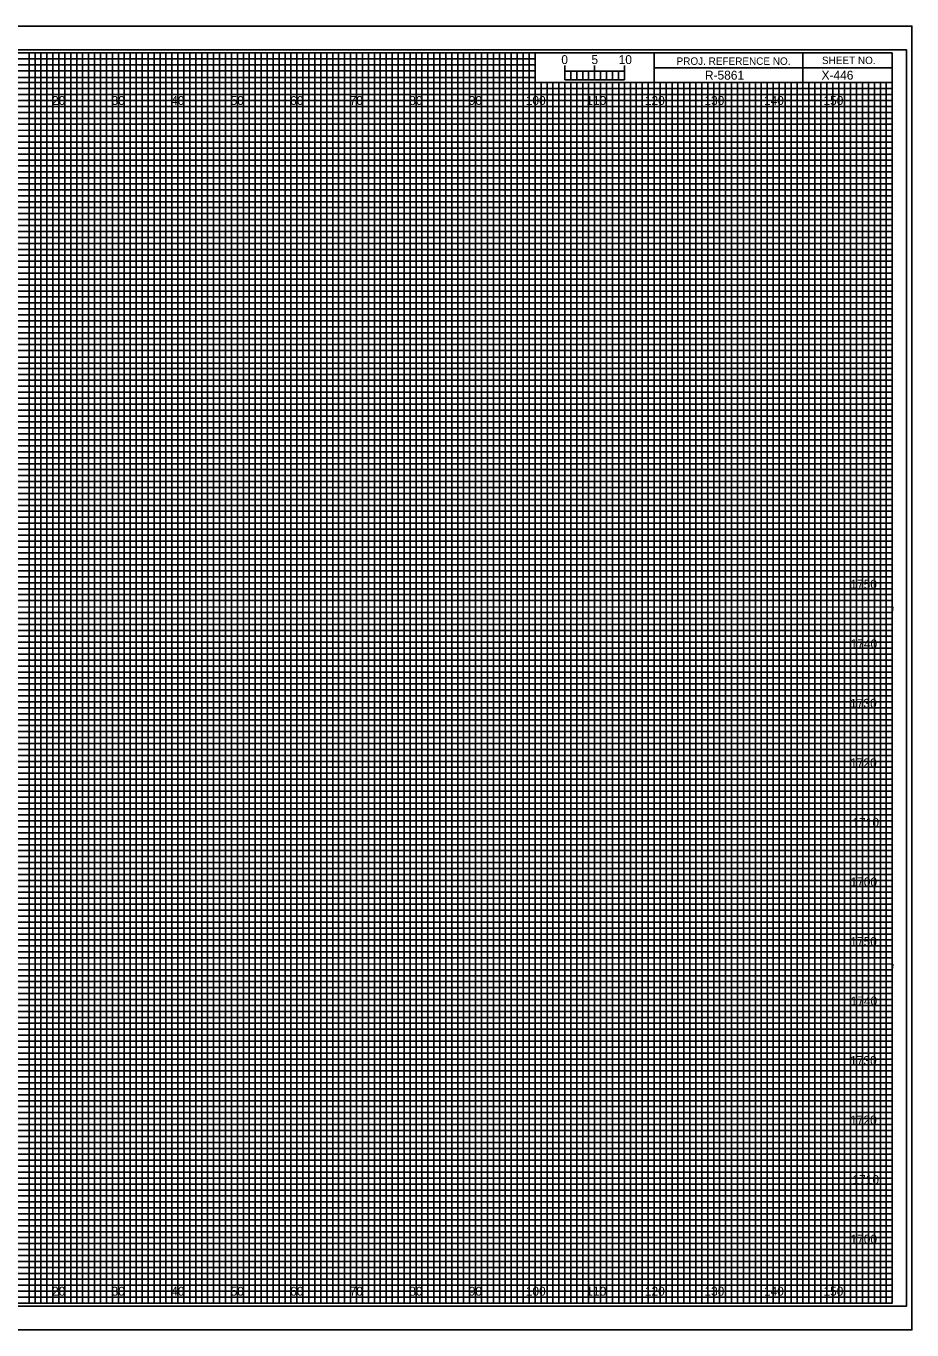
# Model space of a CAD drawing. Extents: x -13 to 323, y -5 to 1314.
# Drawn here: x 174.5 to 323.3, y 1095.5 to 1314.5 of the extents above; entities that cross this region are included whole.
import ezdxf

# ---------------------------------------------------------------- set-up
doc = ezdxf.new("R2010")
doc.units = 0
for name, color, linetype in [('Prop XS Bar Scale Labels', 7, 'Continuous'), ('Prop XS Project Number', 7, 'Continuous'), ('Prop XS Sheet Number', 7, 'Continuous'), ('Raster_Level_0', 7, 'Continuous'), ('Scratch_Level_3', 7, 'Continuous'), ('Sheet Cross Section CELL', 7, 'Continuous'), ('Sheet Cross Section Grid Major CELL', 7, 'Continuous'), ('Sheet Cross Section Grid Middle CELL', 7, 'Continuous'), ('Sheet Cross Section Grid Minor 1 CELL', 7, 'Continuous'), ('Sheet Cross Section Grid Minor 2 CELL', 7, 'Continuous'), ('Sheet Cross Section Scale CELL', 7, 'Continuous'), ('Sheet Cutting Line CELL', 7, 'Continuous'), ('Sheet DOT Grid CELL', 7, 'Continuous'), ('Sheet Plot Border Inside CELL', 7, 'Continuous'), ('Sheet Plot Border Outside CELL', 7, 'Continuous')]:
    doc.layers.add(name, color=color, linetype=linetype)

msp = doc.modelspace()

# ---------------------------------------------------------------- linework, layer by layer
at = {"layer": 'Sheet Cross Section CELL'}
for p, q in [((305, 1310), (305, 1305)), ((305, 1305), (305, 1310)), ((280, 1307.5), (280, 1305)), ((320, 1307.49), (280, 1307.49)), ((280, 1305), (320, 1305))]:
    msp.add_line(p, q, dxfattribs=at)
for points in [[(320, 1310), (0, 1310), (0, 1100), (320, 1100)], [(280, 1310), (260, 1310), (260, 1305.03), (280, 1305.03)], [(320, 1310), (280, 1310), (280, 1305), (320, 1305)]]:
    msp.add_lwpolyline(points, close=True, dxfattribs=at)
at = {"layer": 'Sheet Cross Section Grid Major CELL'}
for p, q in [((190, 1310), (180, 1310)), ((180, 1310), (180, 1100)), ((190, 1100), (190, 1310)), ((210, 1310), (200, 1310)), ((200, 1310), (200, 1100)), ((210, 1100), (210, 1310)), ((230, 1310), (220, 1310)), ((220, 1310), (220, 1100)), ((230, 1100), (230, 1310)), ((250, 1310), (240, 1310)), ((240, 1310), (240, 1100)), ((250, 1100), (250, 1310)), ((260, 1310), (260, 1100)), ((270, 1100), (270, 1305)), ((290, 1305), (280, 1305)), ((280, 1305), (280, 1100)), ((290, 1100), (290, 1305)), ((310, 1305), (300, 1305)), ((300, 1305), (300, 1100)), ((310, 1100), (310, 1305)), ((180, 1100), (170, 1100)), ((200, 1100), (190, 1100)), ((220, 1100), (210, 1100)), ((240, 1100), (230, 1100)), ((260, 1100), (250, 1100)), ((280, 1100), (270, 1100)), ((300, 1100), (290, 1100)), ((320, 1100), (310, 1100)), ((320, 1100), (320, 1100))]:
    msp.add_line(p, q, dxfattribs=at)
for points in [[(0, 1300), (320, 1300), (320, 1290), (0, 1290)], [(0, 1280), (320, 1280), (320, 1270), (0, 1270)], [(0, 1260), (320, 1260), (320, 1250), (0, 1250)], [(0, 1240), (320, 1240), (320, 1230), (0, 1230)], [(0, 1220), (320, 1220), (320, 1210), (0, 1210)], [(0, 1200), (320, 1200), (320, 1190), (0, 1190)], [(0, 1180), (320, 1180), (320, 1170), (0, 1170)], [(0, 1160), (320, 1160), (320, 1150), (0, 1150)], [(0, 1140), (320, 1140), (320, 1130), (0, 1130)], [(0, 1120), (320, 1120), (320, 1110), (0, 1110)]]:
    msp.add_lwpolyline(points, dxfattribs=at)
at = {"layer": 'Sheet Cross Section Grid Middle CELL'}
for points in [[(165, 1100), (175, 1100), (175, 1310), (185, 1310), (185, 1100), (195, 1100), (195, 1310), (205, 1310), (205, 1100), (215, 1100), (215, 1310), (225, 1310), (225, 1100), (235, 1100), (235, 1310), (245, 1310), (245, 1100), (255, 1100), (255, 1310), (259.93, 1310), (260, 1310), (260, 1305), (264.99, 1305), (264.99, 1100), (275, 1100), (275, 1305), (285, 1305), (285, 1100), (295, 1100), (295, 1305), (305, 1305), (305, 1100), (315, 1100), (315, 1305)], [(0, 1305), (275, 1305)], [(0, 1285), (320, 1285), (320, 1295), (0, 1295)], [(0, 1265), (320, 1265), (320, 1275), (0, 1275)], [(0, 1245), (320, 1245), (320, 1255), (0, 1255)], [(0, 1225), (320, 1225), (320, 1235), (0, 1235)], [(0, 1205), (320, 1205), (320, 1215), (0, 1215)], [(0, 1185), (320, 1185), (320, 1195), (0, 1195)], [(0, 1165), (320, 1165), (320, 1175), (0, 1175)], [(0, 1145), (320, 1145), (320, 1155), (0, 1155)], [(0, 1125), (320, 1125), (320, 1135), (0, 1135)], [(0, 1105), (320, 1105), (320, 1115), (0, 1115)]]:
    msp.add_lwpolyline(points, dxfattribs=at)
at = {"layer": 'Sheet Cross Section Grid Minor 1 CELL'}
for p, q in [((0, 1309), (260, 1309)), ((260, 1307.98), (0, 1307.98)), ((260, 1309), (260, 1307.98)), ((0, 1307), (260, 1307)), ((260, 1305.89), (0, 1305.89)), ((260, 1307), (260, 1305.89)), ((0, 1304), (320, 1304))]:
    msp.add_line(p, q, dxfattribs=at)
for points in [[(0, 1303), (270, 1303), (320, 1303), (320, 1302), (0, 1302)], [(0, 1301), (320, 1301), (320, 1299), (0, 1299)], [(0, 1298), (320, 1298), (320, 1297), (0, 1296.98)], [(0, 1296), (320, 1296), (320, 1294), (0, 1294)], [(0, 1293), (320, 1293), (320, 1292), (0, 1292)], [(0, 1291), (320, 1291), (320, 1289), (0, 1289)], [(0, 1288), (320, 1288), (320, 1287), (0, 1287)], [(0, 1286), (320, 1286), (320, 1284), (0, 1284)], [(0, 1283), (320, 1283), (320, 1282), (0, 1282)], [(0, 1281), (320, 1281), (320, 1279), (0, 1279)], [(0, 1278), (320, 1278), (320, 1277), (0, 1277)], [(0, 1276), (320, 1276), (320, 1273.95), (320, 1273), (320, 1272), (0, 1272)], [(0, 1274), (320, 1274), (320, 1273), (0, 1273)], [(0, 1271), (320, 1271), (320, 1269), (0, 1269.03)], [(0, 1269.03), (320, 1269), (320, 1268), (0, 1268)], [(0, 1267), (320, 1267), (320, 1266), (0, 1266)], [(0, 1264), (320, 1264), (320, 1263), (0, 1263)], [(0, 1262), (320, 1262), (320, 1261), (0, 1261)], [(-0.07, 1258.89), (320, 1258.89), (320, 1257.88), (-0.07, 1257.88)], [(0, 1257), (320, 1257), (320, 1256), (0, 1256)], [(0, 1254), (320, 1254), (320, 1253), (0, 1253)], [(0, 1252), (320, 1252), (320, 1251), (0, 1251)], [(0, 1249), (320, 1249), (320, 1248), (0, 1248)], [(0, 1247), (320, 1247), (320, 1246), (0, 1246)], [(0, 1244), (320, 1244), (320, 1243), (0, 1243)], [(0, 1242), (320, 1242), (320, 1241), (0, 1241)], [(0, 1239), (320, 1239), (319.99, 1237.98), (0, 1238)], [(0, 1237), (320, 1237), (320, 1236), (0, 1236)], [(0, 1234), (320, 1234), (320, 1233), (0, 1233)], [(0, 1232), (320, 1232), (320, 1231), (0, 1231)], [(0, 1229), (320, 1229), (320, 1228), (0, 1228)], [(0, 1227), (320, 1227), (320, 1226), (0, 1226)], [(0, 1224), (320, 1224), (320, 1223), (0, 1223)], [(0, 1222), (320, 1222), (320, 1221), (0, 1221)], [(0, 1219), (320, 1219), (320, 1218), (0, 1218)], [(0, 1216.99), (320.07, 1216.91), (320, 1216), (0, 1216)], [(0, 1214), (320, 1214), (320, 1213), (0, 1213)], [(0, 1212), (320, 1212), (320, 1211), (0, 1211)], [(0, 1209), (320, 1209), (320, 1208), (0, 1208)], [(0, 1207), (320, 1207), (320, 1206), (0, 1206)], [(0, 1204), (320, 1204), (320, 1203), (0, 1203)], [(0, 1202), (320, 1202), (320, 1201), (0, 1201)], [(0, 1199), (320, 1199), (320, 1198), (0, 1198)], [(0, 1197), (320, 1197), (320, 1196), (0, 1196)], [(0, 1194), (320, 1194), (320, 1193), (0, 1193)], [(0, 1192), (320, 1192), (320, 1191), (0, 1191)], [(0, 1189), (320, 1189), (320, 1188), (0, 1188)], [(0, 1187), (320, 1187), (320, 1186), (0, 1186)], [(0, 1184), (320, 1184), (320, 1183), (0, 1183)], [(0, 1182), (320, 1182), (320, 1181), (0, 1181)], [(0, 1179), (320, 1179), (319.99, 1177.98), (0, 1178)], [(0, 1177), (320, 1177), (320, 1176), (0, 1176)], [(0, 1174), (320, 1174), (320, 1173), (0, 1173)], [(0, 1172), (320, 1172), (320, 1171), (0, 1171)], [(0, 1169), (320, 1169), (320, 1168), (0, 1168)], [(0, 1167), (320, 1167), (320, 1166), (0, 1166)], [(0, 1164), (320, 1164), (320, 1163), (0, 1163)], [(0, 1162), (320, 1162), (320, 1161), (0, 1161)], [(0, 1159), (320, 1159), (320, 1158), (0, 1158)], [(0, 1156.99), (320.07, 1156.91), (320, 1156), (0, 1156)], [(0, 1154), (320, 1154), (320, 1153), (0, 1153)], [(0, 1152), (320, 1152), (320, 1151), (0, 1151)], [(0, 1149), (320, 1149), (320, 1148), (0, 1148)], [(0, 1147), (320, 1147), (320, 1146), (0, 1146)], [(0, 1144), (320, 1144), (320, 1143), (0, 1143)], [(0, 1142), (320, 1142), (320, 1141), (0, 1141)], [(0, 1139), (320, 1139), (320, 1138), (0, 1138)], [(0, 1137), (320, 1137), (320, 1136), (0, 1136)], [(0, 1134), (320, 1134), (320, 1133), (0, 1133)], [(0, 1132), (320, 1132), (320, 1131), (0, 1131)], [(0, 1129), (320, 1129), (320, 1128), (0, 1128)], [(0, 1127), (320, 1127), (320, 1126), (0, 1126)], [(0, 1124), (320, 1124), (320, 1123), (0, 1123)], [(0, 1122), (320, 1122), (320, 1121), (0, 1121)], [(0, 1119), (320, 1119), (320, 1118), (0, 1118)], [(0, 1117), (320, 1117), (320, 1116), (0, 1116)], [(0, 1114), (320, 1114), (320, 1113), (0, 1113)], [(0, 1112), (320, 1112), (320, 1111), (0, 1111)], [(0, 1109), (320, 1109), (320, 1108), (0, 1108)], [(0, 1107), (320, 1107), (320, 1106), (0, 1106)], [(0, 1104), (320, 1104), (320, 1103), (0, 1103)], [(0, 1102), (320, 1102), (320, 1101), (0, 1101)]]:
    msp.add_lwpolyline(points, dxfattribs=at)
at = {"layer": 'Sheet Cross Section Grid Minor 2 CELL'}
for p, q in [((267, 1305), (266.01, 1305)), ((266.01, 1305), (266.01, 1100)), ((267, 1100), (267, 1305)), ((269, 1305), (268, 1305)), ((268, 1305), (268, 1100)), ((269, 1100), (269, 1305)), ((266.01, 1100), (265, 1100)), ((268, 1100), (267, 1100))]:
    msp.add_line(p, q, dxfattribs=at)
for points in [[(175, 1100), (176, 1100), (176, 1310), (177, 1310), (177, 1100)], [(177, 1100), (178, 1100), (178, 1310), (179, 1310), (179, 1100)], [(180, 1100), (181, 1100), (181, 1310), (182, 1310), (182, 1100)], [(182, 1100), (183, 1100), (183, 1310), (184, 1310), (184, 1100)], [(185, 1100), (186, 1100), (186, 1310), (187, 1310), (187, 1100)], [(187, 1100), (188, 1100), (188, 1310), (189, 1310), (189, 1100)], [(190, 1100), (191, 1100), (191, 1310), (192, 1310), (192, 1100)], [(192, 1100), (193, 1100), (193, 1310), (194, 1310), (194, 1100)], [(195, 1100), (196, 1100), (196, 1310), (197, 1310), (197, 1100)], [(197, 1100), (198, 1100), (198, 1310), (199, 1310), (199, 1100)], [(200, 1100), (201, 1100), (201, 1310), (202, 1310), (202, 1100)], [(202, 1100), (203, 1100), (203, 1310), (204, 1310), (204, 1100)], [(205, 1100), (206, 1100), (206, 1310), (207, 1310), (207, 1100)], [(207, 1100), (208, 1100), (208, 1310), (209, 1310), (209, 1100)], [(210, 1100), (211, 1100), (211, 1310), (212, 1310), (212, 1100)], [(212, 1100), (213, 1100), (213, 1310), (214, 1310), (214, 1100)], [(215, 1100), (216, 1100), (216, 1310), (217, 1310), (217, 1100)], [(217, 1100), (218, 1100), (218, 1310), (219, 1310), (219, 1100)], [(220, 1100), (221, 1100), (221, 1310), (222, 1310), (222, 1100)], [(222, 1100), (223, 1100), (223, 1310), (224, 1310), (224, 1100)], [(225, 1100), (226, 1100), (226, 1310), (227, 1310), (227, 1100)], [(227, 1100), (228, 1100), (228, 1310), (229, 1310), (229, 1100)], [(230, 1100), (231, 1100), (231, 1310), (232, 1310), (232, 1100)], [(232, 1100), (233, 1100), (233, 1310), (234, 1310), (234, 1100)], [(235, 1100), (236, 1100), (236, 1310), (237, 1310), (237, 1100)], [(237, 1100), (238, 1100), (238, 1310), (239, 1310), (239, 1100)], [(240, 1100), (241, 1100), (241, 1310), (242, 1310), (242, 1100)], [(242, 1100), (243, 1100), (243, 1310), (244, 1310), (244, 1100)], [(245, 1100), (246, 1100), (246, 1310), (247, 1310), (247, 1100)], [(247, 1100), (248, 1100), (248, 1310), (249, 1310), (249, 1100)], [(250, 1100), (251, 1100), (251, 1310), (252, 1310), (252, 1100)], [(252, 1100), (253, 1100), (253, 1310), (254, 1310), (254, 1100)], [(255, 1100), (256, 1100), (256, 1310), (257, 1310), (257, 1100)], [(257, 1100), (258, 1100), (258, 1310), (259, 1310), (259, 1100)], [(260, 1100), (261, 1100), (261, 1305), (262.02, 1305), (262.02, 1100)], [(262, 1100), (263, 1100), (263, 1305), (263.99, 1305), (263.99, 1100)], [(270, 1100), (270.98, 1100), (270.98, 1305), (272, 1305), (272, 1100)], [(272, 1100), (273, 1100), (273, 1305), (274.05, 1305), (274.05, 1100)], [(275, 1100), (276, 1100), (276, 1305), (277, 1305), (277, 1100)], [(277, 1100), (278, 1100), (278, 1305), (279, 1305), (279, 1100)], [(280, 1100), (281, 1100), (281, 1305), (282, 1305), (282, 1100)], [(282, 1100), (283, 1100), (283, 1305), (284, 1305), (284, 1100)], [(285, 1100), (286, 1100), (286, 1305), (287, 1305), (287, 1100)], [(287, 1100), (288, 1100), (288, 1305), (289, 1305), (289, 1100)], [(290, 1100), (291, 1100), (291, 1305), (292, 1305), (292, 1100)], [(292, 1100), (293, 1100), (293, 1305), (294, 1305), (294, 1100)], [(295, 1100), (296, 1100), (296, 1305), (297, 1305), (297, 1100)], [(297, 1100), (298, 1100), (298, 1305), (299, 1305), (299, 1100)], [(300, 1100), (301, 1100), (301, 1305), (302, 1305), (302, 1100)], [(302, 1100), (303, 1100), (303, 1305), (304, 1305), (304, 1100)], [(305, 1100), (306, 1100), (306, 1305), (307, 1305), (307, 1100)], [(307, 1100), (308, 1100), (308, 1305), (309, 1305), (309, 1100)], [(310, 1100), (311, 1100), (311, 1305), (312, 1305), (312, 1100)], [(312, 1100), (313, 1100), (313, 1305), (314, 1305), (314, 1100)], [(315, 1100), (316, 1100), (316, 1305), (317, 1305), (317, 1100)], [(317, 1100), (318, 1100), (318, 1305), (319, 1305), (319, 1100)]]:
    msp.add_lwpolyline(points, dxfattribs=at)
at = {"layer": 'Sheet Cross Section Scale CELL'}
for p, q in [((265, 1305.49), (265, 1307.9)), ((265, 1306.9), (265, 1307.9)), ((270, 1305.49), (270, 1307.9)), ((275, 1305.49), (275, 1307.9)), ((275, 1306.9), (275, 1307.9))]:
    msp.add_line(p, q, dxfattribs=at)
for points in [[(275, 1306.9), (265, 1306.9), (265, 1305.49), (275, 1305.49)], [(265, 1306.9), (266, 1306.9), (266, 1305.49), (265, 1305.49)], [(267, 1306.9), (268, 1306.9), (268, 1305.49), (267, 1305.49)], [(269, 1306.9), (270, 1306.9), (270, 1305.49), (269, 1305.49)], [(271, 1306.9), (272, 1306.9), (272, 1305.49), (271, 1305.49)], [(273, 1306.9), (274, 1306.9), (274, 1305.49), (273, 1305.49)]]:
    msp.add_lwpolyline(points, close=True, dxfattribs=at)
at = {"layer": 'Sheet Cutting Line CELL'}
for p, q in [((323.3, 1314.5), (-13.4, 1314.5)), ((-13.4, 1095.5), (323.3, 1095.5))]:
    msp.add_line(p, q, dxfattribs=at)
at = {"layer": 'Sheet DOT Grid CELL'}
for p, q in [((180, 1100), (180, 1310)), ((190, 1100), (190, 1310)), ((200, 1100), (200, 1310)), ((210, 1100), (210, 1310)), ((220, 1100), (220, 1310)), ((230, 1100), (230, 1310)), ((240, 1100), (240, 1310)), ((250, 1100), (250, 1310)), ((260, 1100), (260, 1304.69)), ((270, 1100), (270, 1304.69)), ((280, 1100), (280, 1304.69)), ((290, 1100), (290, 1304.69)), ((300, 1100), (300, 1304.69)), ((310, 1100), (310, 1304.69)), ((0, 1300), (320, 1300)), ((0, 1290), (320, 1290)), ((0, 1280), (320, 1280)), ((0, 1270), (320, 1270)), ((0, 1260), (320, 1260)), ((0, 1250), (320, 1250)), ((0, 1240), (320, 1240)), ((0, 1230), (320, 1230)), ((0, 1220), (320, 1220)), ((0, 1210), (320, 1210)), ((0, 1200), (320, 1200)), ((0, 1190), (320, 1190)), ((0, 1180), (320, 1180)), ((0, 1170), (320, 1170)), ((0, 1160), (320, 1160)), ((0, 1150), (320, 1150)), ((0, 1140), (320, 1140)), ((0, 1130), (320, 1130)), ((0, 1120), (320, 1120)), ((0, 1110), (320, 1110))]:
    msp.add_line(p, q, dxfattribs=at)
at = {"layer": 'Sheet Plot Border Inside CELL'}
msp.add_lwpolyline([(-10.8, 1099.5), (322.4, 1099.5), (322.4, 1310.5), (-10.8, 1310.5)], close=True, dxfattribs=at)
at = {"layer": 'Sheet Plot Border Outside CELL'}
msp.add_lwpolyline([(-13.4, 1095.5), (323.3, 1095.5), (323.3, 1314.5), (-13.4, 1314.5)], close=True, dxfattribs=at)

# ---------------------------------------------------------------- texts
at = {"layer": 'Prop XS Bar Scale Labels'}
for s, p in [('5', (269.47, 1308.12)), ('10', (274.04, 1308.12))]:
    msp.add_text(s, height=1.5, dxfattribs=at).set_placement(p)
at = {"layer": 'Prop XS Project Number'}
msp.add_text('R-5861', height=1.5, dxfattribs=at).set_placement((288.53, 1305.5))
at = {"layer": 'Prop XS Sheet Number'}
msp.add_text('X-446', height=1.5, dxfattribs=at).set_placement((308.12, 1305.5))
at = {"layer": 'Raster_Level_0'}
for s, p in [('20', (178.86, 1301.25)), ('30', (188.86, 1301.25)), ('40', (198.86, 1301.25)), ('50', (208.86, 1301.25)), ('60', (218.86, 1301.25)), ('70', (228.86, 1301.25)), ('80', (238.86, 1301.25)), ('90', (248.86, 1301.25)), ('100', (258.44, 1301.25)), ('110', (268.62, 1301.25)), ('120', (278.44, 1301.25)), ('130', (288.44, 1301.25)), ('140', (298.44, 1301.25)), ('150', (308.44, 1301.25)), ('20', (178.86, 1101.25)), ('30', (188.86, 1101.25)), ('40', (198.86, 1101.25)), ('50', (208.86, 1101.25)), ('60', (218.86, 1101.25)), ('70', (228.86, 1101.25)), ('80', (238.86, 1101.25)), ('90', (248.86, 1101.25)), ('100', (258.44, 1101.25)), ('110', (268.62, 1101.25)), ('120', (278.44, 1101.25)), ('130', (288.44, 1101.25)), ('140', (298.44, 1101.25)), ('150', (308.44, 1101.25))]:
    msp.add_text(s, height=1.5, dxfattribs=at).set_placement(p)
at = {"layer": 'Scratch_Level_3'}
for s, p in [('1750', (312.96, 1220)), ('1740', (313, 1210)), ('1730', (312.92, 1200)), ('1720', (312.93, 1190)), ('1710', (313.31, 1180)), ('1700', (312.98, 1170)), ('1750', (312.96, 1160)), ('1740', (313, 1150)), ('1730', (312.92, 1140)), ('1720', (312.93, 1130)), ('1710', (313.31, 1120)), ('1700', (312.98, 1110))]:
    msp.add_text(s, height=1.5, dxfattribs=at).set_placement(p)
at = {"layer": 'Sheet Cross Section CELL'}
for s, p in [('PROJ. REFERENCE NO.', (283.77, 1307.99)), ('SHEET NO.', (308.19, 1308.12))]:
    msp.add_text(s, height=1.25, dxfattribs=at).set_placement(p)
at = {"layer": 'Sheet Cross Section Scale CELL'}
msp.add_text('0', height=1.5, dxfattribs=at).set_placement((264.41, 1308.12))

doc.saveas('drawing.dxf')
